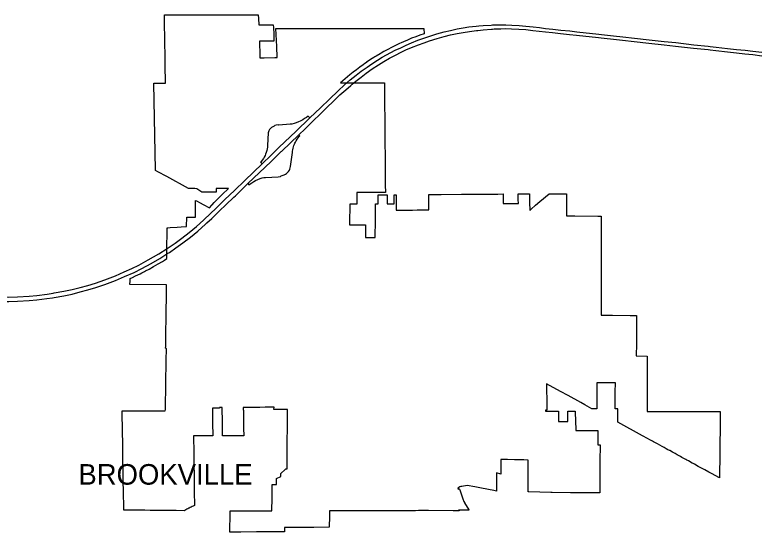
# Model space of a CAD drawing. Extents: x 0 to 34, y 0 to 22.
# Drawn here: x 4.1541 to 4.4446, y 15.5617 to 15.7641 of the extents above; entities that cross this region are included whole.
import ezdxf

# ---------------------------------------------------------------- set-up
doc = ezdxf.new("R2010")
doc.units = 0
for name, color, linetype in [('GM_X_Corporation', 7, 'Continuous'), ('GM_X_Corporation_Text', 7, 'Continuous'), ('GM_X_Interchange_Ramps', 7, 'Continuous'), ('GM_X_Interstate_Route', 7, 'Continuous')]:
    doc.layers.add(name, color=color, linetype=linetype)

msp = doc.modelspace()

# ---------------------------------------------------------------- linework, layer by layer
at = {"layer": 'GM_X_Corporation'}
msp.add_lwpolyline([(4.26022, 15.60975), (4.25537, 15.60975), (4.25537, 15.60981), (4.25544, 15.61055), (4.25461, 15.61055), (4.25459, 15.61055), (4.25457, 15.61055), (4.25455, 15.61055), (4.25453, 15.61055), (4.25451, 15.61055), (4.25291, 15.61055), (4.25194, 15.61055), (4.24982, 15.61054), (4.24878, 15.61054), (4.24861, 15.61054), (4.24859, 15.61054), (4.24857, 15.61054), (4.24855, 15.61054), (4.24853, 15.61054), (4.24851, 15.61054), (4.24711, 15.61054), (4.24709, 15.61054), (4.24707, 15.61054), (4.24705, 15.61054), (4.24703, 15.61054), (4.24701, 15.61054), (4.2454, 15.61054), (4.24466, 15.61054), (4.2434, 15.61053), (4.24341, 15.60973), (4.24342, 15.60925), (4.24353, 15.60237), (4.24357, 15.59939), (4.23922, 15.59938), (4.23533, 15.59938), (4.23532, 15.60021), (4.23523, 15.60573), (4.23518, 15.60924), (4.23517, 15.60972), (4.23516, 15.61052), (4.23407, 15.61052), (4.23406, 15.6102), (4.23406, 15.6102), (4.23258, 15.6102), (4.23134, 15.6102), (4.23135, 15.60971), (4.23135, 15.60923), (4.2314, 15.60586), (4.23142, 15.60365), (4.23147, 15.60021), (4.23148, 15.59937), (4.23019, 15.59937), (4.22891, 15.59937), (4.22395, 15.59936), (4.22398, 15.59712), (4.22401, 15.59481), (4.22404, 15.59239), (4.22411, 15.58734), (4.22414, 15.58477), (4.22416, 15.58299), (4.22417, 15.58238), (4.22422, 15.57876), (4.22425, 15.57647), (4.22429, 15.57337), (4.22431, 15.57211), (4.22387, 15.57193), (4.22344, 15.57173), (4.22302, 15.57154), (4.2226, 15.57133), (4.22219, 15.57111), (4.22211, 15.57107), (4.22177, 15.57089), (4.22137, 15.57066), (4.22096, 15.57043), (4.22056, 15.57018), (4.22042, 15.57009), (4.22039, 15.57009), (4.21712, 15.57013), (4.21494, 15.57015), (4.21411, 15.57016), (4.21342, 15.57017), (4.21254, 15.57018), (4.21123, 15.57019), (4.20878, 15.57022), (4.20697, 15.57024), (4.20488, 15.57027), (4.20073, 15.57031), (4.20021, 15.57032), (4.19672, 15.57033), (4.19667, 15.57297), (4.19663, 15.57585), (4.1965, 15.58355), (4.19637, 15.59107), (4.19628, 15.59664), (4.19621, 15.60075), (4.19607, 15.60919), (4.20208, 15.60919), (4.20963, 15.6092), (4.21275, 15.60921), (4.21293, 15.60921), (4.21294, 15.60969), (4.21295, 15.61017), (4.21329, 15.62905), (4.21337, 15.63348), (4.21306, 15.63364), (4.21307, 15.63432), (4.21309, 15.63567), (4.21313, 15.63792), (4.21314, 15.63889), (4.21317, 15.64078), (4.21319, 15.64202), (4.21321, 15.64333), (4.21323, 15.64469), (4.21325, 15.64614), (4.21327, 15.64758), (4.21328, 15.64848), (4.21329, 15.64895), (4.21331, 15.65031), (4.21334, 15.65173), (4.21337, 15.65398), (4.21339, 15.65527), (4.21341, 15.65663), (4.21343, 15.65785), (4.21344, 15.6585), (4.19911, 15.65855), (4.19913, 15.65997), (4.19914, 15.66094), (4.20008, 15.66138), (4.20124, 15.66192), (4.20304, 15.6628), (4.20379, 15.66318), (4.20483, 15.66371), (4.20523, 15.66392), (4.2066, 15.66465), (4.20836, 15.66562), (4.21009, 15.66662), (4.21181, 15.66765), (4.2126, 15.66814), (4.21352, 15.66871), (4.21357, 15.67451), (4.21357, 15.67461), (4.2136, 15.67745), (4.21363, 15.68024), (4.21363, 15.68076), (4.21395, 15.68078), (4.21485, 15.68083), (4.21751, 15.68099), (4.21913, 15.68109), (4.22124, 15.68122), (4.22128, 15.68498), (4.22134, 15.68498), (4.2235, 15.68497), (4.22471, 15.68497), (4.22478, 15.69144), (4.2251, 15.69127), (4.22649, 15.69053), (4.22773, 15.68987), (4.23017, 15.68858), (4.23111, 15.68964), (4.23122, 15.68977), (4.23198, 15.69062), (4.23344, 15.69207), (4.23454, 15.69316), (4.23515, 15.69376), (4.23762, 15.69611), (4.23765, 15.69614), (4.23573, 15.69614), (4.23289, 15.69615), (4.23284, 15.69615), (4.23284, 15.6947), (4.22725, 15.69471), (4.22523, 15.69608), (4.22444, 15.69611), (4.22304, 15.69617), (4.22209, 15.6962), (4.22205, 15.69621), (4.21355, 15.7008), (4.21, 15.70272), (4.20906, 15.70323), (4.20906, 15.70328), (4.20841, 15.73734), (4.21299, 15.73735), (4.21299, 15.73745), (4.21288, 15.74446), (4.21285, 15.74607), (4.21282, 15.74793), (4.21282, 15.74813), (4.21274, 15.75318), (4.2126, 15.76225), (4.21258, 15.76343), (4.21256, 15.76408), (4.23389, 15.76408), (4.23716, 15.76408), (4.23755, 15.76408), (4.23799, 15.76408), (4.24091, 15.76408), (4.24618, 15.76407), (4.24927, 15.76407), (4.24933, 15.76263), (4.24943, 15.76021), (4.24943, 15.76017), (4.25492, 15.76017), (4.25514, 15.76017), (4.25518, 15.75911), (4.2552, 15.75871), (4.25528, 15.75685), (4.25533, 15.75558), (4.25534, 15.75544), (4.25534, 15.75536), (4.2554, 15.75382), (4.25239, 15.75381), (4.2504, 15.7538), (4.24969, 15.75379), (4.24972, 15.75285), (4.24987, 15.74894), (4.2499, 15.74813), (4.24993, 15.74732), (4.25154, 15.74732), (4.25568, 15.74734), (4.25664, 15.74735), (4.25646, 15.75168), (4.25637, 15.75399), (4.25627, 15.75645), (4.25617, 15.75874), (4.26116, 15.75874), (4.26962, 15.75875), (4.27239, 15.75876), (4.27333, 15.75876), (4.27471, 15.75876), (4.27697, 15.75876), (4.27747, 15.75876), (4.27881, 15.75877), (4.28019, 15.75877), (4.28305, 15.75877), (4.28341, 15.75877), (4.28454, 15.75877), (4.2915, 15.75879), (4.29346, 15.75879), (4.29425, 15.75879), (4.29494, 15.75879), (4.29824, 15.75879), (4.29965, 15.75879), (4.30226, 15.75878), (4.30629, 15.75878), (4.30667, 15.75878), (4.31034, 15.75877), (4.3121, 15.75877), (4.31288, 15.75877), (4.31401, 15.75877), (4.31405, 15.75671), (4.31243, 15.75614), (4.31082, 15.75553), (4.30921, 15.7549), (4.30762, 15.75424), (4.30604, 15.75355), (4.30508, 15.75311), (4.30448, 15.75283), (4.30292, 15.75209), (4.30138, 15.75132), (4.29985, 15.75052), (4.29834, 15.74969), (4.29735, 15.74913), (4.29684, 15.74884), (4.29536, 15.74797), (4.29476, 15.7476), (4.29436, 15.74736), (4.29312, 15.74655), (4.29298, 15.74646), (4.29161, 15.74553), (4.29156, 15.7455), (4.2905, 15.74475), (4.29026, 15.74458), (4.28892, 15.74361), (4.2876, 15.74262), (4.2863, 15.7416), (4.28502, 15.74056), (4.28409, 15.73978), (4.28144, 15.73747), (4.28417, 15.73747), (4.29011, 15.73749), (4.29065, 15.73748), (4.29217, 15.73748), (4.2929, 15.73748), (4.29451, 15.73747), (4.295, 15.73747), (4.29572, 15.73746), (4.29855, 15.73742), (4.29857, 15.73527), (4.29861, 15.73057), (4.29863, 15.7288), (4.29864, 15.72701), (4.29866, 15.72524), (4.29867, 15.72396), (4.29868, 15.72348), (4.29868, 15.72279), (4.2987, 15.72131), (4.2987, 15.72051), (4.29872, 15.71893), (4.29872, 15.71871), (4.29873, 15.71718), (4.29875, 15.71557), (4.29876, 15.71405), (4.29876, 15.71378), (4.29877, 15.71265), (4.29878, 15.71217), (4.29879, 15.71061), (4.29879, 15.71052), (4.29881, 15.70889), (4.29882, 15.70708), (4.29884, 15.70472), (4.29885, 15.70375), (4.29887, 15.70134), (4.29887, 15.70121), (4.29891, 15.69736), (4.29891, 15.69677), (4.29893, 15.69539), (4.29893, 15.69462), (4.2962, 15.69462), (4.29497, 15.69462), (4.29459, 15.69462), (4.29218, 15.69462), (4.2897, 15.69463), (4.28779, 15.69463), (4.28778, 15.69418), (4.28778, 15.69366), (4.28774, 15.69006), (4.28506, 15.69005), (4.28501, 15.69005), (4.28498, 15.68788), (4.28495, 15.6845), (4.28493, 15.68278), (4.28492, 15.68193), (4.28493, 15.68193), (4.29119, 15.68195), (4.29119, 15.68192), (4.29116, 15.67908), (4.29113, 15.67696), (4.29499, 15.67697), (4.29501, 15.67885), (4.29505, 15.68192), (4.29505, 15.68196), (4.29506, 15.68272), (4.29506, 15.68282), (4.29508, 15.68449), (4.29508, 15.68453), (4.29511, 15.68787), (4.29511, 15.68792), (4.29514, 15.69004), (4.29514, 15.69009), (4.29607, 15.69009), (4.29614, 15.69366), (4.29791, 15.69366), (4.29798, 15.69366), (4.29894, 15.69366), (4.29968, 15.69366), (4.29966, 15.6901), (4.2997, 15.6901), (4.30076, 15.69011), (4.30236, 15.69011), (4.30238, 15.69368), (4.30248, 15.69368), (4.30272, 15.69368), (4.30318, 15.69368), (4.30316, 15.69012), (4.30315, 15.68771), (4.30319, 15.68771), (4.30506, 15.68771), (4.30512, 15.68772), (4.30778, 15.68773), (4.30786, 15.68773), (4.30955, 15.68773), (4.31131, 15.68774), (4.3114, 15.68774), (4.31324, 15.68775), (4.31594, 15.68776), (4.31595, 15.69011), (4.31595, 15.69017), (4.31597, 15.69374), (4.31614, 15.69374), (4.31647, 15.69375), (4.32029, 15.6938), (4.32079, 15.69381), (4.32866, 15.69389), (4.33734, 15.69389), (4.339, 15.69391), (4.34043, 15.69394), (4.34096, 15.69395), (4.34104, 15.69395), (4.34177, 15.69396), (4.34286, 15.69398), (4.34495, 15.69401), (4.34495, 15.69233), (4.34495, 15.69029), (4.34512, 15.69029), (4.34756, 15.6903), (4.34799, 15.6903), (4.34955, 15.6903), (4.3509, 15.6903), (4.35088, 15.69183), (4.35084, 15.69405), (4.35238, 15.69404), (4.3545, 15.69405), (4.3553, 15.69406), (4.3553, 15.69373), (4.35531, 15.69082), (4.35533, 15.68759), (4.35588, 15.68806), (4.35765, 15.68958), (4.35935, 15.69104), (4.36294, 15.69412), (4.36444, 15.69403), (4.36974, 15.69403), (4.36974, 15.68548), (4.37258, 15.68544), (4.37304, 15.68544), (4.38194, 15.68532), (4.38325, 15.6853), (4.38325, 15.68465), (4.38326, 15.67367), (4.38326, 15.67005), (4.38326, 15.66687), (4.38326, 15.66499), (4.38326, 15.6599), (4.38326, 15.65658), (4.38326, 15.6518), (4.38326, 15.64658), (4.3861, 15.64656), (4.38776, 15.64655), (4.39464, 15.64649), (4.39567, 15.64649), (4.39707, 15.64647), (4.39706, 15.64347), (4.39705, 15.64261), (4.39702, 15.63557), (4.39702, 15.63378), (4.39701, 15.63224), (4.397, 15.63063), (4.39717, 15.63063), (4.40119, 15.6306), (4.4012, 15.62418), (4.4012, 15.62376), (4.4012, 15.62296), (4.4012, 15.61899), (4.40121, 15.61405), (4.40121, 15.61398), (4.40121, 15.61059), (4.40121, 15.6101), (4.40121, 15.60986), (4.40121, 15.6094), (4.40121, 15.60889), (4.4034, 15.60889), (4.40373, 15.60889), (4.40592, 15.60889), (4.40652, 15.60889), (4.40675, 15.60889), (4.40779, 15.60888), (4.40839, 15.60888), (4.40904, 15.60888), (4.41705, 15.60887), (4.41953, 15.60887), (4.42195, 15.60886), (4.42592, 15.60886), (4.4287, 15.60885), (4.42984, 15.60885), (4.42982, 15.60799), (4.42981, 15.60681), (4.42979, 15.60561), (4.42979, 15.60488), (4.42978, 15.6044), (4.42977, 15.6032), (4.42975, 15.60199), (4.42973, 15.60055), (4.42972, 15.59967), (4.42971, 15.59878), (4.42971, 15.59828), (4.4297, 15.59742), (4.42969, 15.59724), (4.42969, 15.59685), (4.42968, 15.59565), (4.42966, 15.59444), (4.42965, 15.59324), (4.42964, 15.59248), (4.42963, 15.59203), (4.42962, 15.59083), (4.42961, 15.58962), (4.42959, 15.58882), (4.42959, 15.58842), (4.42958, 15.58721), (4.42957, 15.58658), (4.42956, 15.586), (4.42954, 15.5848), (4.42952, 15.58291), (4.42641, 15.58462), (4.42541, 15.58517), (4.42384, 15.58603), (4.42351, 15.58621), (4.42229, 15.58688), (4.42225, 15.5869), (4.42123, 15.58746), (4.41977, 15.58827), (4.41943, 15.58846), (4.41892, 15.58873), (4.41889, 15.58875), (4.41745, 15.58955), (4.41743, 15.58955), (4.41673, 15.58994), (4.41639, 15.59013), (4.41533, 15.59071), (4.41486, 15.59097), (4.41428, 15.59129), (4.41375, 15.59158), (4.41322, 15.59187), (4.41298, 15.592), (4.41216, 15.59245), (4.41111, 15.59303), (4.41005, 15.59361), (4.40999, 15.59364), (4.40937, 15.59398), (4.4087, 15.59435), (4.40789, 15.59479), (4.40706, 15.59525), (4.40619, 15.59573), (4.40527, 15.59623), (4.40426, 15.59678), (4.40369, 15.59709), (4.40337, 15.59727), (4.40224, 15.59789), (4.40142, 15.59834), (4.39946, 15.59942), (4.38984, 15.60468), (4.38984, 15.60724), (4.38983, 15.60894), (4.38983, 15.60942), (4.38983, 15.60991), (4.38943, 15.60991), (4.38879, 15.60991), (4.38879, 15.61172), (4.38879, 15.61202), (4.3888, 15.61429), (4.38881, 15.6155), (4.38881, 15.61632), (4.38881, 15.61744), (4.38882, 15.61925), (4.38882, 15.62019), (4.38672, 15.62018), (4.38506, 15.62017), (4.3848, 15.62017), (4.38455, 15.62017), (4.38443, 15.62017), (4.38159, 15.62016), (4.38158, 15.61746), (4.38157, 15.61581), (4.38157, 15.61464), (4.38156, 15.6116), (4.38155, 15.60994), (4.37969, 15.60994), (4.37685, 15.61151), (4.37528, 15.61237), (4.37032, 15.61511), (4.36732, 15.61677), (4.36732, 15.61676), (4.36195, 15.61972), (4.36195, 15.6195), (4.36196, 15.61848), (4.36202, 15.61244), (4.36204, 15.61045), (4.36204, 15.60997), (4.36205, 15.60948), (4.36155, 15.60948), (4.36155, 15.60944), (4.36155, 15.609), (4.36489, 15.609), (4.36663, 15.60899), (4.36663, 15.60784), (4.36664, 15.6065), (4.36664, 15.60496), (4.37024, 15.60497), (4.37024, 15.60546), (4.37024, 15.60657), (4.37024, 15.60899), (4.37305, 15.60899), (4.37321, 15.60471), (4.37331, 15.60222), (4.37334, 15.60142), (4.37767, 15.60144), (4.382, 15.60146), (4.38193, 15.59587), (4.38286, 15.59587), (4.38272, 15.58938), (4.38274, 15.58374), (4.38275, 15.58092), (4.38277, 15.57712), (4.37422, 15.5771), (4.37131, 15.57716), (4.36408, 15.57728), (4.36358, 15.57729), (4.35504, 15.57744), (4.35479, 15.57744), (4.35479, 15.57941), (4.35478, 15.58384), (4.35478, 15.58617), (4.35477, 15.5899), (4.35301, 15.58995), (4.35196, 15.58997), (4.35132, 15.58999), (4.3507, 15.59001), (4.3494, 15.59004), (4.3467, 15.59011), (4.34401, 15.59018), (4.34402, 15.58444), (4.34243, 15.58493), (4.34242, 15.58188), (4.34242, 15.57828), (4.34242, 15.57774), (4.34133, 15.57796), (4.33655, 15.5789), (4.33385, 15.57944), (4.33091, 15.58002), (4.32886, 15.5796), (4.32843, 15.57951), (4.32802, 15.57943), (4.32801, 15.57942), (4.32767, 15.57924), (4.32719, 15.57897), (4.3272, 15.57895), (4.32736, 15.57851), (4.3278, 15.57875), (4.32784, 15.57878), (4.32802, 15.57829), (4.32926, 15.57479), (4.32966, 15.57368), (4.3298, 15.57329), (4.32988, 15.57317), (4.33156, 15.57041), (4.33157, 15.57039), (4.33158, 15.57037), (4.33141, 15.57037), (4.32756, 15.57038), (4.32751, 15.57038), (4.32777, 15.57014), (4.32779, 15.57012), (4.32547, 15.57012), (4.31577, 15.57013), (4.31427, 15.57013), (4.31308, 15.57013), (4.31189, 15.57013), (4.3107, 15.57012), (4.30951, 15.57012), (4.3083, 15.57012), (4.3075, 15.57012), (4.3063, 15.57012), (4.30543, 15.57012), (4.30519, 15.57012), (4.30408, 15.57012), (4.30297, 15.57011), (4.30186, 15.57011), (4.30075, 15.57011), (4.29979, 15.57011), (4.29964, 15.57011), (4.29853, 15.57011), (4.29742, 15.57011), (4.2963, 15.57011), (4.29524, 15.57011), (4.29393, 15.57011), (4.29252, 15.57011), (4.29092, 15.57011), (4.28915, 15.57011), (4.28786, 15.57011), (4.2866, 15.57011), (4.28627, 15.5701), (4.28379, 15.57009), (4.28187, 15.57008), (4.27898, 15.57007), (4.27706, 15.57006), (4.27705, 15.56912), (4.27704, 15.56798), (4.27698, 15.56361), (4.27103, 15.56358), (4.26877, 15.56357), (4.26481, 15.56355), (4.26477, 15.56355), (4.26014, 15.56353), (4.25984, 15.56353), (4.25983, 15.56353), (4.2595, 15.56353), (4.2595, 15.56342), (4.25949, 15.56185), (4.25729, 15.56184), (4.25258, 15.56181), (4.24856, 15.56178), (4.24249, 15.56174), (4.24071, 15.56173), (4.2382, 15.56172), (4.2382, 15.56293), (4.23821, 15.56804), (4.23822, 15.57008), (4.24095, 15.57009), (4.24673, 15.57009), (4.24771, 15.57009), (4.2522, 15.57009), (4.25459, 15.5701), (4.25461, 15.57179), (4.25463, 15.57351), (4.25466, 15.57523), (4.25468, 15.57695), (4.25471, 15.57867), (4.25471, 15.58039), (4.25632, 15.5804), (4.25634, 15.58158), (4.25637, 15.5827), (4.25804, 15.58347), (4.25804, 15.5846), (4.25811, 15.58465), (4.25824, 15.58478), (4.25967, 15.58614), (4.25972, 15.58619), (4.25993, 15.58639), (4.25999, 15.58645), (4.26001, 15.58646), (4.26004, 15.5865), (4.26053, 15.5865), (4.26053, 15.58696), (4.26052, 15.58853), (4.26052, 15.58872), (4.26052, 15.58872), (4.26053, 15.58972), (4.26054, 15.59076), (4.26055, 15.5912), (4.26055, 15.5915), (4.26055, 15.59223), (4.26058, 15.59545), (4.26059, 15.5963), (4.2606, 15.59714), (4.26061, 15.59939), (4.26062, 15.60044), (4.26062, 15.60063), (4.26063, 15.60117), (4.26063, 15.60203), (4.26064, 15.60316), (4.26066, 15.60428), (4.26067, 15.60653), (4.2607, 15.60926), (4.2607, 15.60975)], close=True, dxfattribs=at)
at = {"layer": 'GM_X_Interchange_Ramps'}
for points in [[(4.26942, 15.72377), (4.26878, 15.72442), (4.26812, 15.72398), (4.26739, 15.72352), (4.26662, 15.72307), (4.2656, 15.72252), (4.26495, 15.72218), (4.26409, 15.72183), (4.2633, 15.72161), (4.26234, 15.72137), (4.26172, 15.72132), (4.25732, 15.72095), (4.25719, 15.721)], [(4.25719, 15.721), (4.25622, 15.72091), (4.25571, 15.72075), (4.25541, 15.72059), (4.25494, 15.72032), (4.25447, 15.72001), (4.25403, 15.71961), (4.25368, 15.71919), (4.25337, 15.71867), (4.25322, 15.71832), (4.25309, 15.7179), (4.25289, 15.71296), (4.25284, 15.71232), (4.25274, 15.71169), (4.2526, 15.71101), (4.25237, 15.71024), (4.25212, 15.70955), (4.25189, 15.70905), (4.25157, 15.70842), (4.25124, 15.70787), (4.25083, 15.70728), (4.25023, 15.7065), (4.25015, 15.70641), (4.25073, 15.70577)], [(4.2579, 15.70083), (4.25825, 15.70106), (4.25901, 15.70136), (4.25935, 15.70155), (4.2599, 15.70181), (4.26031, 15.70208), (4.26074, 15.70246), (4.26108, 15.70284), (4.2614, 15.70333), (4.26161, 15.70377), (4.26176, 15.70423), (4.26189, 15.70475), (4.26266, 15.71023), (4.2627, 15.71073), (4.26277, 15.7113), (4.26289, 15.71192), (4.26302, 15.7124), (4.26319, 15.71291), (4.2634, 15.71346), (4.26357, 15.71385), (4.26379, 15.71426), (4.2641, 15.71479), (4.26448, 15.71541), (4.26523, 15.71646), (4.26551, 15.71675), (4.26509, 15.71717)], [(4.24516, 15.69808), (4.24561, 15.6976), (4.24609, 15.69793), (4.24678, 15.69839), (4.24754, 15.69887), (4.24823, 15.69929), (4.24909, 15.69972), (4.24999, 15.70006), (4.25074, 15.70027), (4.25146, 15.70041), (4.25208, 15.70049), (4.25709, 15.70076), (4.2579, 15.70083)]]:
    msp.add_lwpolyline(points, dxfattribs=at)
at = {"layer": 'GM_X_Interstate_Route'}
msp.add_line((4.23969, 15.6927), (4.24031, 15.6933), dxfattribs=at)
for points in [[(4.26942, 15.72377), (4.27358, 15.72777), (4.27706, 15.73109), (4.28043, 15.73431), (4.28293, 15.73669), (4.28518, 15.7386), (4.28748, 15.74046), (4.28948, 15.74202), (4.29177, 15.74363), (4.29368, 15.74491), (4.29589, 15.74633), (4.29772, 15.74747), (4.29937, 15.74839), (4.30103, 15.74929), (4.3028, 15.75022), (4.30495, 15.75124), (4.30702, 15.75221), (4.3091, 15.75316), (4.31161, 15.75414), (4.31401, 15.755), (4.3163, 15.75579), (4.31906, 15.75662), (4.32194, 15.75742), (4.32433, 15.75801), (4.32697, 15.75856), (4.32934, 15.75897), (4.3315, 15.75933), (4.33438, 15.75968), (4.33541, 15.75978)], [(4.33541, 15.75978), (4.33713, 15.75993), (4.34026, 15.76009), (4.34078, 15.76011), (4.34153, 15.76016), (4.34389, 15.76018), (4.34601, 15.76018), (4.34833, 15.7601), (4.3512, 15.75995), (4.35389, 15.75964), (4.35671, 15.75933), (4.35912, 15.7591), (4.36157, 15.75879), (4.36436, 15.7585), (4.3675, 15.75815), (4.37099, 15.75777), (4.37377, 15.75749), (4.37741, 15.75707), (4.3812, 15.75664), (4.38453, 15.75629), (4.38811, 15.75589), (4.39169, 15.75548), (4.39626, 15.75498), (4.40201, 15.75432), (4.40792, 15.75371), (4.41241, 15.75321), (4.41948, 15.75241), (4.4251, 15.75181), (4.42589, 15.75172), (4.42816, 15.75147), (4.43271, 15.75097), (4.43619, 15.75058), (4.43954, 15.75022), (4.44261, 15.74987), (4.44609, 15.74945)], [(4.28601, 15.73698), (4.28742, 15.73818), (4.28941, 15.73975), (4.29141, 15.74125), (4.29378, 15.7429), (4.29621, 15.74452), (4.29832, 15.74582), (4.30061, 15.74707), (4.30288, 15.74833), (4.30509, 15.74945), (4.30697, 15.75033), (4.30921, 15.75133), (4.31183, 15.75234), (4.31404, 15.75319), (4.31619, 15.75396), (4.31913, 15.75488), (4.32191, 15.75563), (4.3244, 15.75625), (4.32694, 15.75681), (4.32928, 15.75721), (4.33185, 15.75763), (4.33459, 15.75798), (4.33502, 15.75802)], [(4.33502, 15.75802), (4.3371, 15.75824), (4.34038, 15.75849), (4.34078, 15.75852), (4.34144, 15.75855), (4.344, 15.75862), (4.34593, 15.75868), (4.34828, 15.75861), (4.35108, 15.75848), (4.35381, 15.7583), (4.35663, 15.75799), (4.35905, 15.75775), (4.36149, 15.75745), (4.36428, 15.75715), (4.36743, 15.75681), (4.37092, 15.75643), (4.37369, 15.75615), (4.37734, 15.75573), (4.38112, 15.7553), (4.38446, 15.75495), (4.38803, 15.75454), (4.39162, 15.75414), (4.39619, 15.75364), (4.40194, 15.75298), (4.40784, 15.75237), (4.41234, 15.75186), (4.4194, 15.75107), (4.42503, 15.75047), (4.4259, 15.75037), (4.42809, 15.75013), (4.43264, 15.74963), (4.43611, 15.74924), (4.43946, 15.74888), (4.44254, 15.74853), (4.44601, 15.74811)], [(4.26753, 15.71953), (4.27063, 15.72255), (4.27358, 15.72531), (4.2812, 15.73274), (4.28346, 15.73476), (4.28538, 15.73644), (4.28601, 15.73698)], [(4.25073, 15.70577), (4.25433, 15.70923), (4.25708, 15.7119), (4.25746, 15.71227), (4.26392, 15.71848), (4.26942, 15.72377)], [(4.25843, 15.71077), (4.26509, 15.71717), (4.26753, 15.71953)], [(4.25424, 15.70672), (4.2555, 15.70793), (4.25755, 15.70991), (4.25825, 15.71059), (4.25843, 15.71077)], [(4.1691, 15.6552), (4.16951, 15.65527), (4.17332, 15.65595), (4.17649, 15.65661), (4.17963, 15.65743), (4.18262, 15.65821), (4.1856, 15.65916), (4.18926, 15.66042), (4.19351, 15.66205), (4.19691, 15.66353), (4.19984, 15.66484), (4.20263, 15.66621), (4.20619, 15.66821), (4.21038, 15.67055), (4.2137, 15.67269), (4.21679, 15.67481), (4.21938, 15.67673), (4.22229, 15.67899), (4.22515, 15.68133), (4.22783, 15.68371), (4.23073, 15.68648), (4.23253, 15.68821), (4.23315, 15.6888), (4.23625, 15.69179), (4.23998, 15.69539), (4.24395, 15.69927), (4.25073, 15.70577)], [(4.24031, 15.6933), (4.24056, 15.69354), (4.24516, 15.69808), (4.2519, 15.70447), (4.25424, 15.70672)], [(4.22921, 15.6827), (4.23108, 15.68445), (4.23377, 15.68703), (4.23411, 15.68735), (4.23661, 15.68971), (4.23969, 15.6927)], [(4.2145, 15.67117), (4.21707, 15.67292), (4.21974, 15.67483), (4.22274, 15.67716), (4.2256, 15.67949), (4.22865, 15.68217), (4.22921, 15.6827)], [(4.16881, 15.65341), (4.1695, 15.65352), (4.17331, 15.65421), (4.17648, 15.65486), (4.17962, 15.65569), (4.1826, 15.65647), (4.18582, 15.65743), (4.18933, 15.65859), (4.19342, 15.66017), (4.19704, 15.66169), (4.20073, 15.66334), (4.20369, 15.6648), (4.20743, 15.66683), (4.21074, 15.6688), (4.21395, 15.67079), (4.2145, 15.67117)], [(3.9917, 15.65505), (4.00539, 15.65493), (4.01883, 15.65482), (4.03264, 15.65471), (4.05387, 15.65453), (4.06782, 15.6544), (4.08029, 15.65429), (4.08189, 15.65429), (4.08512, 15.65428), (4.09443, 15.65418), (4.11506, 15.65401), (4.13316, 15.65384), (4.14592, 15.65375), (4.15175, 15.65366), (4.15515, 15.65377), (4.1597, 15.65405), (4.16268, 15.6543), (4.16669, 15.65481), (4.1691, 15.6552)], [(3.99169, 15.65325), (4.00537, 15.65318), (4.01881, 15.65308), (4.03262, 15.65297), (4.05386, 15.65278), (4.0678, 15.65266), (4.08027, 15.65255), (4.082, 15.65254), (4.0851, 15.65253), (4.09441, 15.65244), (4.11505, 15.65227), (4.13314, 15.6521), (4.1459, 15.652), (4.15174, 15.65192), (4.15513, 15.65203), (4.15968, 15.65231), (4.16267, 15.65256), (4.16667, 15.65306), (4.16881, 15.65341)]]:
    msp.add_lwpolyline(points, dxfattribs=at)

# ---------------------------------------------------------------- texts
at = {"layer": 'GM_X_Corporation_Text'}
msp.add_text('BROOKVILLE', height=0.008037, rotation=0, dxfattribs=at).set_placement((4.17894, 15.5803))

doc.saveas('drawing.dxf')
